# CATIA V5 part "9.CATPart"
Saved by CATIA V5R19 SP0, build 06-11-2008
Part number: 9
Bounding box of the stored display mesh (mm): x -25 to 145, y -189.905 to 114.984, z 5 to 110
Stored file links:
  G:\EU_thinkMotion\CFAO_2010\MMS_groupe3\MMS_groupe3\A reprendre\bblot\BLOT\9.CATPart
  J:\CFAO_IFMA\Amortisseur.CATProduct
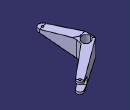
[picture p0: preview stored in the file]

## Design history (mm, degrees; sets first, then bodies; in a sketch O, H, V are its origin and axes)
External parameters (linked from other documents)
  `External.Diamètre 9-11` = 20 mm
Set1
  Plane1 "Plan 9-11": linked copy from another document
  Point1: linked copy from another document
  Point2 "C": linked copy from another document
  Plane2 "Dessus 9": linked copy from another document
  Line1: linked copy from another document
  Line2: linked copy from another document
  Plane3 "Plan 8-9 dessus": linked copy from another document
  Plane4 "Plan 8-9 dessous": linked copy from another document
  Line3: linked copy from another document
Set2
  Plane5: type 2Lines, Element1 Line1, Element2 Line2
  Plane6: type 2Lines, Element1 Line4, Element2 Line2
  Line4: stored without definition
  DatumCurve1
Body1 (main body)
  Sketch1 on Plane1, origin (0, 0, 30), H (1, 0, 0), V (0, 1, 0)
    circle A1 centre (35, -170) radius 5
    point P1 (35, -170)
    reference projected point E1 (35, -170) from Point1
    circle A2 centre (130, 100) radius 5
    point P2 (130, 100)
    reference projected point E2 (130, 100) from Point2
    circle A3 centre (0, 0) radius 20
    point P3 (-25, -30.2941)
    line L1 (-25, -30.2941) -> (15.7446, -175.4065)
    arc A4 centre (35, -170) radius 20 from (15.7446, -175.4065) to (54.6013, -166.0266) ccw
    point P5 (35, -170)
    arc A5 centre (130, 100) radius 15 from (139.0942, 88.0713) to (121.98, 112.676) ccw
    point P8 (130, 100)
    reference projected point E3 (130, 100) from Point2
    reference projected point E4 (35, -170) from Point1
    line L2 (54.6013, -166.0266) -> (25, -20)
    point P10 (25, -20)
    line L3 (25, -20) -> (25, 1.0881)
    line L4 (25, 1.0881) -> (139.0942, 88.0713)
    line L5 (121.98, 112.676) -> (-25, 19.683)
    line L6 (-25, 19.683) -> (-25, -30.2941)
    construction line L7 (0, 0) -> (35, -170)
    construction line L8 (-25, -30.2941) -> (25, -20)
    point P13 (-25, -30.2941)
    point P14 (25, -20)
    construction line L9 (25, -20) -> (0, -20)
    point P15 (0, -20)
    construction line L10 (130, 100) -> (0, 0)
    radius A3 = 20 {= `External.Diamètre 9-11`}
    radius A1 = 5 {= `External.Diamètre 9-11` /4}
    radius A2 = 5 {= `External.Diamètre 9-11` /4}
    radius A4 = 20 {= `External.Diamètre 9-11` /2+10mm}
    distance L3 A3 = 5
    distance A3 L6 = 5
    radius A5 = 15 {= `External.Diamètre 9-11` /2+5mm}
    angle L4 L5 = 5
    distance A3 L5 = 10
    coincidence: P1 E1, P2 E2, P8 E3, P5 E4, P14 P10, P13 P3, P15 A3
    tangency: A4 L1, L4 A5, L2 A4, A5 L5, L9 A3
    vertical: L3 V, L6 V
    perpendicularity: L8 L7
    horizontal: L9 H
  Pad1: profile Sketch1, direction (0, 0, 1), up to Plane2
  Sketch2 on Plane5, origin (0, 0, 0), H (-0.7926, -0.6097, 0), V (0, 0, 1)
    line L1 (-234.0122, 110) -> (-234.0122, 55)
    line L2 (-234.0122, 55) -> (-164.0122, 55)
    point P3 (-164.0122, 55)
    line L3 (-164.0122, 55) -> (7.8147, 110)
    point P4 (7.8147, 110)
    line L4 (7.8147, 110) -> (-234.0122, 110)
    reference projected point E1 (7.8147, 110) from vertex [face of Pad1 from Sketch1.L6 | face of Pad1 from Sketch1.L5 | end face of Pad1]
    reference projected line E2 through (-164.0122, 0) direction (0, 1) from Line1
    reference projected line E3 through (-164.0122, 0) direction (0, 1) from Line1
    reference intersected line E4 through (0, 45) direction (-1, 0) from Plane3
    line L5 (-234.0122, 45) -> (-134.0122, 45)
    point P6 (-134.0122, 45)
    arc A1 centre (-134.0122, 30) radius 15 from (-134.0122, 45) to (-119.0122, 30) cw
    line L6 (-119.0122, 30) -> (-234.0122, 30)
    line L7 (-234.0122, 30) -> (-234.0122, 45)
    reference projected line E5 (-330.639, 30) -> (-29.0559, 30) from edge [start face of Pad1 | face of Pad1 from Sketch1.L5]
    reference intersected line E6 through (0, 45) direction (-1, 0) from Plane3
    axis line L8 (-119.0122, 30) -> (-119.0122, 68.4706)
    reference projected line E7 through (-164.0122, 0) direction (0, 1) from Line1
    distance E3 L1 = 70
    distance L2 E4 = 10
    distance P6 E7 = 30
    vertical: L1 V, L7 V, L8 V
    horizontal: L2 H, L4 H, L5 H, L6 H
    coincidence: P4 E1, P3 E2, E5 L6, L7 L1, L5 E6
    tangency: A1 L5, L8 A1
  Pocket1: profile Sketch2, direction (0.6097, -0.7926, 0), through (limit type 3), opposite side through (limit type 3)
  SolidCombine1: FirstComponentProfile Sketch4, FirstComponentDirection Sketch4, SecondComponentProfile Sketch5, SecondComponentDirection Sketch5
  Sketch3 on Plane6, origin (0, 0, 0), H (-0.2017, 0.9795, 0), V (0, 0, 1)
    line L1 (-24.6305, 110) -> (-173.5655, 90)
    point P1 (-24.6305, 110)
    point P2 (-173.5655, 90)
    line L2 (-173.5655, 90) -> (-233.5655, 90)
    line L3 (-233.5655, 90) -> (-233.5655, 75)
    line L4 (-233.5655, 75) -> (-173.5655, 75)
    point P5 (-173.5655, 75)
    line L5 (-173.5655, 75) -> (-24.6305, 30)
    point P6 (-24.6305, 30)
    reference projected point E1 (-24.6305, 110) from vertex [face of Pad1 from Sketch1.L6 | face of Pad1 from Sketch1.L1 | end face of Pad1]
    reference projected line E2 (-132.5148, 30) -> (63.3766, 30) from edge of DatumCurve1
    line L6 (-24.6305, 110) -> (-24.6305, 140)
    line L7 (-24.6305, 140) -> (-263.5655, 140)
    line L8 (-263.5655, 140) -> (-263.5655, 0)
    line L9 (-263.5655, 0) -> (-24.6305, 0)
    line L10 (-24.6305, 0) -> (-24.6305, 30)
    point P11 (-24.6305, 30)
    reference projected line E3 (-24.6305, 30) -> (-24.6305, 110) from edge [face of Pad1 from Sketch1.L3 | face of Pad1 from Sketch1.L2]
    reference projected line E4 through (-173.5655, 0) direction (0, 1) from Line3
    reference projected line E5 through (-173.5655, 0) direction (0, 1) from Line3
    reference projected line E6 (-175.6161, 110) -> (-27.6553, 110) from edge [face of Pad1 from Sketch1.L2 | end face of Pad1]
    reference projected line E7 through (-173.5655, 0) direction (0, 1) from Line3
    distance L8 L3 = 30
    distance E6 L2 = 20
    length L6 = 30
    length L10 = 30
    distance E7 L3 = 60
    length L3 = 15
    horizontal: L2 H, L4 H, L7 H, L9 H
    vertical: L3 V, L6 V, L8 V, L10 V
    coincidence: P1 E1, E2 P6, P11 P6, P6 E3, P2 E4, P5 E5
  Pocket2: profile Sketch3, direction (-0.9795, -0.2017, 0), through (limit type 3), opposite side through (limit type 3)
  Sketch4 on Plane4, origin (0, 0, 15), H (1, 0, 0), V (0, 1, 0)
    point P1 (121.98, 112.676)
    line L1 (121.98, 112.676) -> (-25, 19.683)
    point P2 (-25, 19.683)
    line L2 (-25, 19.683) -> (25, 1.0881)
    point P3 (25, 1.0881)
    line L3 (25, 1.0881) -> (139.0942, 88.0713)
    point P4 (139.0942, 88.0713)
    arc A1 centre (130, 100) radius 15 from (139.0942, 88.0713) to (121.98, 112.676) ccw
    point P6 (121.98, 112.676)
    point P7 (139.0942, 88.0713)
    reference projected arc E1 centre (130, 100) radius 15 from (143.99, 94.589) to (117.0731, 107.6088) ccw from edge [face of Pad1 from Sketch1.A5 | face of Pocket1 from Sketch2.L2]
    reference projected line E2 (-48.869, 4.5813) -> (204.7946, 165.072) from edge [face of Pocket1 from Sketch2.L3 | face of Pad1 from Sketch1.L5]
    reference projected line E3 (38.8652, 11.6586) -> (275.9581, 192.4135) from edge [face of Pad1 from Sketch1.L4 | face of Pocket1 from Sketch2.L3]
    reference projected point E4 (-25, 19.683) from vertex [face of Pocket1 from Sketch2.L3 | end face of Pad1 | face of Pad1 from Sketch1.L6 | face of Pad1 from Sketch1.L5]
    reference projected point E5 (25, 1.0881) from vertex [face of Pad1 from Sketch1.L3 | face of Pad1 from Sketch1.L4 | face of Pocket1 from Sketch2.L3]
    coincidence: P6 L1, P6 P1, P7 P4, A1 E1, L1 E2, L3 E3, P2 E4, P3 E5
  Sketch5 on Plane5, origin (0, 0, 0), H (-0.7926, -0.6097, 0), V (0, 0, 1)
    line L1 (7.8147, 30) -> (-167.6973, 5)
    point P1 (7.8147, 30)
    line L2 (-167.6973, 5) -> (-194.0122, 5)
    line L3 (-194.0122, 5) -> (-194.0122, 15)
    line L4 (-194.0122, 15) -> (-134.0122, 15)
    arc A1 centre (-134.0122, 30) radius 15 from (-134.0122, 15) to (-119.0122, 30) ccw
    line L5 (-119.0122, 30) -> (7.8147, 30)
    point P8 (7.8147, 30)
    reference projected line E1 (-330.639, 30) -> (-29.0559, 30) from edge [start face of Pad1 | face of Pad1 from Sketch1.L5]
    reference projected arc E2 centre (-134.0122, 30) radius 15 from (-119.0122, 30) to (-134.0122, 45) ccw from edge [face of Pad1 from Sketch1.L5 | face of Pocket1 from Sketch2.A1]
    reference projected line E3 through (-164.0122, 0) direction (0, 1) from Line1
    reference projected point E4 (7.8147, 30) from vertex [face of Pad1 from Sketch1.L6 | face of Pad1 from Sketch1.L5 | start face of Pad1]
    distance E3 L3 = 30
    length L3 = 10
    distance A1 L1 = 5
    horizontal: L2 H, L4 H
    vertical: L3 V
    tangency: A1 L4
    coincidence: P8 L1, L5 E1, A1 E2, P8 P1, P1 E4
